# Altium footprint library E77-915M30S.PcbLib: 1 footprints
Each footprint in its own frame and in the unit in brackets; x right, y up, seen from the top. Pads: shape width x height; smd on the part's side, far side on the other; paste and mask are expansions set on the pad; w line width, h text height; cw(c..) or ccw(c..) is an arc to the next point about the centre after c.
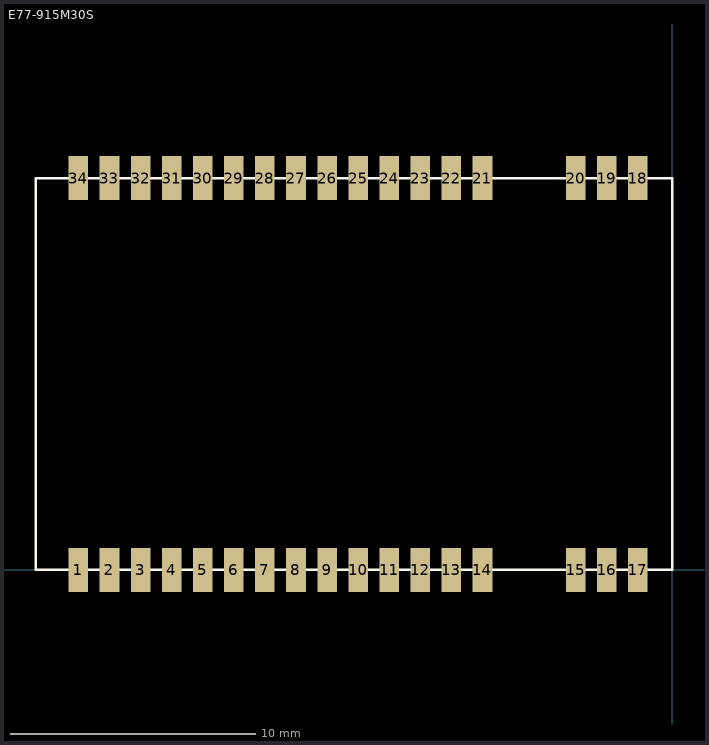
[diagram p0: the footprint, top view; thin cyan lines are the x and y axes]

## E77-915M30S [mm]
pads (34):
  rect 0.8x1.8 smd: 1(-24.26,0) 2(-22.99,0) 3(-21.72,0) 4(-20.45,0) 5(-19.18,0) 6(-17.91,0) 7(-16.64,0) 8(-15.37,0) 9(-14.1,0) 10(-12.83,0) 11(-11.56,0) 12(-10.29,0) 13(-9.02,0) 14(-7.75,0) 15(-3.94,0) 16(-2.67,0) 17(-1.4,0) 18(-1.4,16) 19(-2.67,16) 20(-3.94,16) 21(-7.75,16) 22(-9.02,16) 23(-10.29,16) 24(-11.56,16) 25(-12.83,16) 26(-14.1,16) 27(-15.37,16) 28(-16.64,16) 29(-17.91,16) 30(-19.18,16) 31(-20.45,16) 32(-21.72,16) 33(-22.99,16) 34(-24.26,16)
Top Overlay:
  lines w0.1: -26,0 -26,16 0,16 0,0 -26,0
